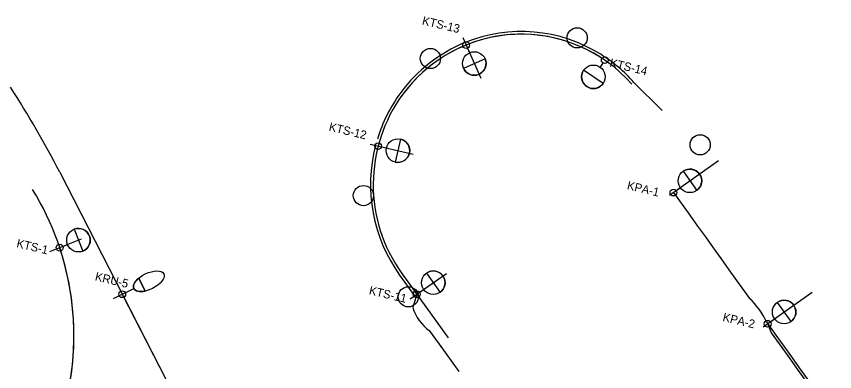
# Model space of a CAD drawing. Extents: x 0 to 511877, y 0 to 6211921.
# Drawn here: x 511731.4 to 511853, y 6211867.9 to 6211920.7 of the extents above; entities that cross this region are included whole.
import ezdxf

# ---------------------------------------------------------------- set-up
doc = ezdxf.new("R2010")
doc.units = 0
for name, color, linetype in [('Help', 7, 'Continuous'), ('Lys Kommunalt', 7, 'Continuous'), ('TV_U_LYS_Ledn-', 7, 'Continuous'), ('TV_U_LYS_Mastenummer', 7, 'Continuous'), ('TV_U_LYS_Nyx330-Trafiksti', 7, 'Continuous'), ('TV_U_LYS_Nyx450-Rundkørsel', 7, 'Continuous')]:
    doc.layers.add(name, color=color, linetype=linetype)

msp = doc.modelspace()

# ---------------------------------------------------------------- linework, layer by layer
at = {"layer": 'Help'}
for p, q in [((511797.74, 6211917.51), (511800.42, 6211911.51)), ((511827.38, 6211906.68), (511823.12, 6211910.91)), ((511783.99, 6211901.66), (511790.4, 6211900.21)), ((511828.47, 6211894.09), (511835.74, 6211899.26)), ((511737.87, 6211897.5), (511753.64, 6211866.78)), ((511736.4, 6211885.73), (511741.11, 6211887.6)), ((511788.37, 6211882.23), (511790.57, 6211879.16)), ((511788.7, 6211882.46), (511795.56, 6211872.92)), ((511789.93, 6211878.71), (511795.32, 6211882.47)), ((511747.7, 6211879.65), (511745.79, 6211878.72)), ((511842.38, 6211874.53), (511849.64, 6211879.7))]:
    msp.add_line(p, q, dxfattribs=at)
for centre, radius, start, end in [((511806.46, 6211896.15), 22.26, 58.0784, 112.1377), ((511806.46, 6211896.15), 21.86, 41.3592, 143.6703), ((511806.46, 6211896.15), 22.26, 112.1377, 143.6703), ((511806.46, 6211896.15), 22.26, 41.3592, 58.0784), ((511606.44, 6211830), 147.75, 27.1845, 32.8498), ((511807.1, 6211895.68), 22.66, 143.6703, 215.6812), ((511807.1, 6211895.68), 23.06, 143.6703, 162.9309), ((511807.1, 6211895.68), 23.06, 165.4159, 215.6812), ((511698.44, 6211873.22), 41.55, 344.1199, 31.5529)]:
    msp.add_arc(centre, radius, start, end, dxfattribs=at)
at = {"layer": 'Lys Kommunalt'}
for centre in [(511814.73, 6211917.48), (511792.94, 6211914.41), (511833, 6211901.59), (511782.98, 6211894.04), (511789.66, 6211879.01)]:
    msp.add_circle(centre, 1.5, dxfattribs=at)
at = {"layer": 'TV_U_LYS_Ledn-'}
for p, q in [((511788.7, 6211882.46), (511790.9, 6211879.4)), ((511747.17, 6211879.38), (511753.64, 6211866.78)), ((511790.9, 6211879.39), (511790.31, 6211877.41)), ((511843.04, 6211875), (511843.57, 6211873.65)), ((511792.77, 6211873.98), (511794.22, 6211871.96)), ((511794.22, 6211871.96), (511797.14, 6211867.89))]:
    msp.add_line(p, q, dxfattribs=at)
for points in [[(511829.04, 6211894.5), (511831.46, 6211891.13), (511832.62, 6211889.52), (511833.78, 6211887.91), (511834.93, 6211886.29), (511836.11, 6211884.65), (511837.28, 6211883.03), (511838.42, 6211881.43), (511839.6, 6211879.79), (511840.32, 6211878.78)], [(511842.85, 6211875.27), (511843.06, 6211874.98), (511844.23, 6211873.33), (511845.41, 6211871.7), (511846.55, 6211870.1), (511847.71, 6211868.48), (511848.89, 6211866.83), (511850.06, 6211865.2), (511851.24, 6211863.57), (511852.4, 6211861.95), (511852.98, 6211861.15)], [(511843.57, 6211873.65), (511845.12, 6211871.49), (511846.27, 6211869.9), (511847.43, 6211868.27), (511849.39, 6211865.54)]]:
    msp.add_lwpolyline(points, dxfattribs=at)
for centre, radius, start, end in [((511806.46, 6211896.15), 21.86, 55.5042, 143.6703), ((511807.1, 6211895.68), 22.66, 143.6703, 215.6812), ((511698.44, 6211873.22), 41.55, 344.1199, 18.4149), ((511833.53, 6211871.24), 10.15, 23.4001, 47.9803), ((511796.76, 6211879.45), 6.77, 197.5494, 233.8623)]:
    msp.add_arc(centre, radius, start, end, dxfattribs=at)
at = {"layer": 'TV_U_LYS_Nyx330-Trafiksti'}
for p, q in [((511798.44, 6211915.94), (511798.74, 6211915.26)), ((511801.06, 6211914.37), (511797.86, 6211912.94)), ((511801.06, 6211914.37), (511801.06, 6211914.37)), ((511818.55, 6211913.75), (511818.13, 6211913.13)), ((511818.58, 6211910.7), (511815.69, 6211912.68)), ((511818.58, 6211910.7), (511818.58, 6211910.7)), ((511788.49, 6211902.44), (511787.72, 6211899.02)), ((511788.49, 6211902.44), (511788.49, 6211902.44)), ((511785.67, 6211901.28), (511786.4, 6211901.12)), ((511830.47, 6211897.66), (511832.5, 6211894.8)), ((511830.47, 6211897.66), (511830.47, 6211897.66)), ((511829.44, 6211894.78), (511830.05, 6211895.21)), ((511740.02, 6211889.05), (511741.31, 6211885.79)), ((511740.02, 6211889.05), (511740.02, 6211889.05)), ((511738.34, 6211886.5), (511739.03, 6211886.77)), ((511792.37, 6211882.54), (511794.37, 6211879.67)), ((511792.37, 6211882.54), (511792.37, 6211882.54)), ((511791.31, 6211879.68), (511791.93, 6211880.11)), ((511844.46, 6211878.18), (511846.49, 6211875.33)), ((511844.46, 6211878.18), (511844.46, 6211878.18)), ((511843.44, 6211875.3), (511844.05, 6211875.74))]:
    msp.add_line(p, q, dxfattribs=at)
for centre, radius in [((511798.23, 6211916.4), 0.5), ((511799.46, 6211913.66), 1.75), ((511818.83, 6211914.16), 0.5), ((511817.14, 6211911.69), 1.75), ((511785.18, 6211901.39), 0.5), ((511788.11, 6211900.73), 1.75), ((511831.48, 6211896.23), 1.75), ((511829.03, 6211894.49), 0.5), ((511740.66, 6211887.42), 1.75), ((511737.87, 6211886.31), 0.5), ((511793.37, 6211881.1), 1.75), ((511790.9, 6211879.39), 0.5), ((511845.48, 6211876.76), 1.75), ((511843.03, 6211875.01), 0.5)]:
    msp.add_circle(centre, radius, dxfattribs=at)
for centre, start, end in [((511799.46, 6211913.66), 204.0596, 23.9896), ((511817.14, 6211911.69), 145.5482, 325.4782), ((511788.11, 6211900.73), 257.2843, 77.2144), ((511831.48, 6211896.23), 305.4622, 125.3922), ((511740.66, 6211887.42), 291.6674, 111.5974), ((511793.37, 6211881.1), 304.7843, 124.7143), ((511845.48, 6211876.76), 305.4622, 125.3922)]:
    msp.add_arc(centre, 1.75, start, end, dxfattribs=at)
at = {"layer": 'TV_U_LYS_Nyx450-Rundkørsel'}
for p, q in [((511749.63, 6211881.78), (511750.57, 6211879.86)), ((511750.57, 6211879.86), (511749.63, 6211881.78)), ((511747.62, 6211879.61), (511748.88, 6211880.22))]:
    msp.add_line(p, q, dxfattribs=at)
msp.add_circle((511747.17, 6211879.39), 0.5, dxfattribs=at)
msp.add_ellipse((511751.11, 6211881.32), major_axis=(2.23, 1.09), ratio=0.483744, dxfattribs=at)
msp.add_ellipse((511751.11, 6211881.32), major_axis=(2.23, 1.09), ratio=0.483744, start_param=2.042184, end_param=4.239581, dxfattribs=at)

# ---------------------------------------------------------------- texts
at = {"layer": 'TV_U_LYS_Mastenummer'}
for s, p in [('KTS-13', (511791.62, 6211919.48)), ('KTS-14', (511819.48, 6211913.21)), ('KTS-12', (511777.77, 6211903.7)), ('KPA-1', (511822.06, 6211895)), ('KTS-1', (511731.38, 6211886.4)), ('KRU-5', (511743.03, 6211881.47)), ('KTS-11', (511783.73, 6211879.41)), ('KPA-2', (511836.27, 6211875.43))]:
    msp.add_text(s, height=1.25, rotation=346.664, dxfattribs=at).set_placement(p)

doc.saveas('drawing.dxf')
